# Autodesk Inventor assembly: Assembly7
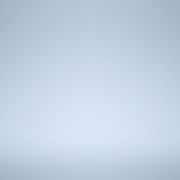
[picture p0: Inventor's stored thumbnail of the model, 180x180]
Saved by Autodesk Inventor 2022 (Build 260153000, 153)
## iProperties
Created: 2024-10
Part Number: Assembly7
Document SubType Name: Assembly
Designer: shimizu
Author: shimizu
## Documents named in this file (1)
- C:\Users\shimizu\Documents\卒論2024\3DCAD\ギアボックス\部品図\Assembly7.iam
